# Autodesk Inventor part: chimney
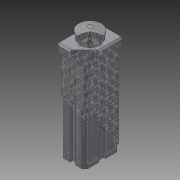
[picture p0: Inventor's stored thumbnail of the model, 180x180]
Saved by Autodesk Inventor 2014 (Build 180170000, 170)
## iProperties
Created: 2013-07
Part Number: chimney
Material: Generic
Document SubType Name: Modeling
Designer: Brent J. Rosenburgh
Density: 1 g/cm^3
Appearance: Default
Author: Brent J. Rosenburgh
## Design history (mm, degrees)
sketch "Sketch1"
  geometry: L1 (6.23, 11.74)-(-6.244, 11.74); L2 (-6.245, -11.748)-(-8.244, -9.708); L3 (-6.244, 11.74)-(-8.244, 9.74); L4 (8.23, 9.74)-(6.23, 11.74); L5 (6.23, -11.748)-(8.23, -9.748); L6 (-8.244, 2.133)-(-6.862, 2.133); L7 (-6.862, 2.133)-(-6.862, -0.609); L8 (-6.862, -0.609)-(-8.244, -1.991); L9 (8.23, 2.133)-(6.867, 2.133); L10 (6.867, 2.133)-(6.867, -0.609); L11 (6.867, -0.609)-(8.23, -1.972); L12 (-8.244, 9.74)-(-8.244, 2.133); L13 (-8.244, -1.991)-(-8.244, -9.708); L14 (8.23, -9.748)-(8.23, -1.972); L15 (8.23, 2.133)-(8.23, 9.74); L16 (-1.68, -11.748)-(-1.68, -9.875); L17 (-1.68, -9.875)-(1.667, -9.875); L18 (1.667, -9.875)-(1.667, -11.748); L19 (-6.245, -11.748)-(-1.68, -11.748); L20 (1.667, -11.748)-(6.23, -11.748); L21 (-2.966, 8.462)-(2.624, 8.462); L22 (4.624, 6.462)-(4.624, -6.141); L23 (2.624, -8.141)-(-2.966, -8.141); L24 (-4.966, -6.141)-(-4.966, 6.462); L25 (-2.966, 8.462)-(-4.966, 6.462); L26 (2.624, 8.462)-(4.624, 6.462); L27 (4.624, -6.141)-(2.624, -8.141); L28 (-2.966, -8.141)-(-4.966, -6.141); 1 further point
  constraints: 56 end point, 12 perpendicular, 11 parallel, 3 horizontal
extrude "Extrusion1" new body sketch "Sketch1" distance "d0" = 60; taper "d1" = 0 deg
sketch "Sketch2"
  geometry: L1 (-8.244, -9.708)-(-6.245, -11.748) reference; L2 (-1.68, -11.748)-(-1.68, -9.875) reference; L3 (-1.68, -9.875)-(1.667, -9.875) reference; L4 (1.667, -9.875)-(1.667, -11.748) reference; L5 (6.23, -11.748)-(8.23, -9.748) reference; L6 (-8.244, -1.991)-(-8.244, -9.708) reference; L7 (-8.244, -9.708)-(-8.244, -11.748); L8 (-8.244, -11.748)-(-6.245, -11.748); L9 (-1.68, -11.748)-(1.667, -11.748); L10 (6.23, -11.748)-(8.23, -11.748); L11 (8.23, -11.748)-(8.23, -9.748); 1 further point
  constraints: 10 end point, 3 collinear, 2 perpendicular
extrude "Extrusion2" join sketch "Sketch2" distance "d2" = 24; taper "d3" = 0 deg
chamfer "Chamfer2" distance "d7" = 1.8; stored, may be unused: second distance "d8" = 2, angle "d9" = 45 deg
sketch "Sketch3"
  geometry: L1 (0, 0)-(36, 0) reference; L2 (36, -2.04)-(36, 0) reference; L3 (36, -2.04)-(33.184, 0); 1 further point
  constraints: 2 end point, 1 point on line
extrude "Extrusion3" join sketch "Sketch3" distance "d10" = 16.47472; taper "d11" = 0 deg
sketch "Sketch4"
  geometry: L1 (8.23, -1.972)-(6.867, -0.609) reference; L2 (6.867, -0.609)-(6.867, 2.133) reference; L3 (6.867, 2.133)-(8.23, 2.133) reference; L4 (-8.244, 2.133)-(-6.862, 2.133) reference; L5 (-6.862, 2.133)-(-6.862, -0.609) reference; L6 (-6.862, -0.609)-(-8.244, -1.991) reference; L7 (-8.244, -1.991)-(-8.244, -11.748) reference; L8 (-8.244, 2.133)-(-8.244, -1.991); L9 (8.23, 2.133)-(8.23, -1.972); 1 further point
  constraints: 4 end point, 1 collinear, 1 parallel
extrude "Extrusion4" join sketch "Sketch4" distance "d12" = 38.02528; taper "d13" = 0 deg
sketch "Sketch5"
  geometry: L1 (33.184, 0)-(36, -2.04) reference; L2 (0, 11.841)-(21.975, 11.841) reference; L3 (21.975, 7.717)-(21.975, 11.841) reference; L4 (21.975, 7.717)-(16.281, 11.841); 1 further point
  constraints: 2 end point, 1 parallel, 1 point on line
extrude "Extrusion5" join sketch "Sketch5" distance "d14" = 2.22472; taper "d15" = 0 deg
sketch "Sketch6"
  geometry: L1 (-36, -2)-(-33.239, 0) reference; L2 (-21.975, 11.881)-(-21.975, 7.776) reference; L3 (0, 11.881)-(-21.975, 11.881) reference; L4 (-21.975, 7.776)-(-16.308, 11.881); 1 further point
  constraints: 2 end point, 1 parallel, 1 point on line
extrude "Extrusion6" join sketch "Sketch6" distance "d16" = 1.77528; taper "d17" = 0 deg
sketch "Sketch7"
  geometry: L1 (8.23, 9.74)-(6.23, 11.74) reference; L2 (-6.244, 11.74)-(-8.244, 9.74) reference; L3 (-8.244, 9.74)-(-8.244, -11.748) reference; L4 (-6.244, 11.74)-(-8.244, 11.74); L5 (-8.244, 11.74)-(-8.244, 9.74); L6 (6.23, 11.74)-(8.23, 11.74); L7 (8.23, 11.74)-(8.23, 9.74); 1 further point
  constraints: 8 end point, 4 perpendicular
extrude "Extrusion7" join sketch "Sketch7" distance "d18" = 54.47472; taper "d19" = 0 deg
sketch "Sketch8"
  geometry: L1 (5.525, 19.448)-(5.525, 21.448) reference; L2 (16.281, 11.841)-(21.975, 7.717) reference; L3 (0, 7.717)-(21.975, 7.717) reference; L4 (5.525, 19.448)-(2.764, 21.448); L5 (2.764, 21.448)-(5.525, 21.448); 1 further point
  constraints: 4 end point, 2 parallel
extrude "Extrusion8" join sketch "Sketch8" distance "d20" = 16.47472; taper "d21" = 0 deg
chamfer "Chamfer3" distance "d22" = 1.8; stored, may be unused: second distance "d23" = 2, angle "d24" = 45 deg
chamfer "Chamfer4" distance "d25" = 1.4; stored, may be unused: second distance "d26" = 2, angle "d27" = 45 deg
chamfer "Chamfer5" distance "d28" = 0.5; stored, may be unused: second distance "d29" = 2, angle "d30" = 45 deg
sketch "Sketch9"
  geometry: L1 (7.73, 11.74)-(8.23, 11.24) reference; L2 (7.73, 11.74)-(-7.744, 11.74) reference; L3 (-8.244, 11.24)-(-7.744, 11.74) reference; L4 (-8.244, 11.24)-(-8.244, -11.248) reference; L5 (-7.744, -11.748)-(-8.244, -11.248) reference; L6 (-7.744, -11.748)-(7.73, -11.748) reference; L7 (8.23, -11.248)-(7.73, -11.748) reference; L8 (8.23, -11.248)-(8.23, 11.24) reference; 1 further point
extrude "Extrusion9" join sketch "Sketch9" distance "d31" = 1.47472; taper "d32" = 45 deg
sketch "Sketch10"
  geometry: L1 (9.705, 11.851)-(9.705, -11.859) reference; L2 (8.341, 13.215)-(9.705, 11.851) reference; L3 (-8.355, 13.215)-(8.341, 13.215) reference; L4 (-9.719, 11.851)-(-8.355, 13.215) reference; L5 (-9.719, -11.859)-(-9.719, 11.851) reference; L6 (-8.355, -13.223)-(-9.719, -11.859) reference; L7 (8.341, -13.223)-(-8.355, -13.223) reference; L8 (9.705, -11.859)-(8.341, -13.223) reference; 1 further point
extrude "Extrusion10" join sketch "Sketch10" distance "d33" = 4; taper "d34" = 0 deg
sketch "Sketch11"
  geometry: L1 (9.705, -11.859)-(9.705, 11.851) reference; L2 (9.705, 11.851)-(8.341, 13.215) reference; L3 (8.341, 13.215)-(-8.355, 13.215) reference; L4 (-8.355, 13.215)-(-9.719, 11.851) reference; L5 (-9.719, 11.851)-(-9.719, -11.859) reference; L6 (-9.719, -11.859)-(-8.355, -13.223) reference; L7 (-8.355, -13.223)-(8.341, -13.223) reference; L8 (8.341, -13.223)-(9.705, -11.859) reference; 1 further point
extrude "Extrusion11" join sketch "Sketch11" distance "d35" = 1; taper "d36" = -45 deg
sketch "Sketch12"
  geometry: C1 r 5.597 at (0, 0); 1 further point
  constraints: 1 centre point, 1 coincident
extrude "Extrusion12" cut sketch "Sketch12" distance "d37" = 6.5; taper "d38" = 0 deg
chamfer "Chamfer6" distance "d39" = 0.5; stored, may be unused: second distance "d40" = 2, angle "d41" = 45 deg
chamfer "Chamfer7" distance "d42" = 5.5; stored, may be unused: second distance "d43" = 2, angle "d44" = 45 deg
chamfer "Chamfer8" distance "d45" = 5.75; stored, may be unused: second distance "d46" = 2, angle "d47" = 45 deg
sketch "Sketch13"
  geometry: L1 (0.5, -7)-(-0.5, -7); L2 (-0.5, -7)-(-0.5, 7); L3 (-0.5, 7)-(0.5, 7); L4 (0.5, 7)-(0.5, -7); L5 (0.5, -7)-(-0.5, 7); L6 (-0.5, -7)-(0.5, 7); L7 (-7, -0.5)-(7, -0.5); L8 (7, -0.5)-(7, 0.5); L9 (7, 0.5)-(-7, 0.5); L10 (-7, 0.5)-(-7, -0.5); L11 (4.596, -5.303)-(5.303, -4.596); L12 (5.303, -4.596)-(-4.596, 5.303); L13 (-5.303, 4.596)-(4.596, -5.303); L14 (-4.596, 5.303)-(-5.303, 4.596); L15 (4.596, 5.303)-(-5.303, -4.596); L16 (-5.303, -4.596)-(-4.596, -5.303); L17 (-4.596, -5.303)-(5.303, 4.596); L18 (5.303, 4.596)-(4.596, 5.303); C1 r 5.597 at (0, 0) reference
  constraints: 36 end point, 8 parallel, 4 perpendicular, 2 horizontal, 2 midpoint
  dimensions: "d48" = 1 distance of L2.end L3.end
extrude "Extrusion13" join sketch "Sketch13" distance "d49" = 4; taper "d50" = 0 deg
chamfer "Chamfer9" distance "d51" = 4.25; stored, may be unused: second distance "d52" = 2, angle "d53" = 45 deg
chamfer "Chamfer10" distance "d54" = 1; stored, may be unused: second distance "d55" = 2, angle "d56" = 45 deg
sketch "Sketch14"
  geometry: C1 r 7.018 at (0, 0); 1 further point
  constraints: 1 centre point, 1 coincident
extrude "Extrusion14" join sketch "Sketch14" distance "d57" = 0.6; taper "d58" = 45 deg
sketch "Sketch15"
  geometry: C1 r 7.618 at (0, 0) reference
extrude "Extrusion15" join sketch "Sketch15" distance "d59" = 1; taper "d60" = 0 deg
sketch "Sketch16"
  geometry: C1 r 7.618 at (0, 0) reference
extrude "Extrusion16" join sketch "Sketch16" distance "d61" = 2; taper "d62" = 0 deg
chamfer "Chamfer11" distance "d63" = 6; stored, may be unused: second distance "d64" = 2, angle "d65" = 45 deg
sketch "Sketch17"
  geometry: L1 (60, 23.948)-(56, 23.948); L2 (56, 23.948)-(56, 14.948); L3 (56, 14.948)-(60, 14.948); L4 (60, 14.948)-(60, 23.948); L5 (56, 14)-(56, 5); L6 (60, 14)-(56, 14); L7 (60, 5)-(60, 14); L8 (56, 5)-(60, 5); L9 (56, 4)-(56, -5); L10 (60, 4)-(56, 4); L11 (60, -5)-(60, 4); L12 (56, -5)-(60, -5); L13 (51, 18.779)-(51, 9.779); L14 (51, 28.727)-(51, 19.727); L15 (51, 8.779)-(51, -0.221); L16 (55, -0.221)-(55, 8.779); L17 (51, -0.221)-(55, -0.221); L18 (55, 8.779)-(51, 8.779); L19 (55, 9.779)-(55, 18.779); L20 (51, 9.779)-(55, 9.779); L21 (51, 19.727)-(55, 19.727); L22 (55, 28.727)-(51, 28.727); L23 (55, 19.727)-(55, 28.727); L24 (55, 18.779)-(51, 18.779); L25 (51, -1.111)-(51, -10.111); L26 (55, -10.111)-(55, -1.111); L27 (51, -10.111)-(55, -10.111); L28 (55, -1.111)-(51, -1.111); L29 (46, 14.948)-(50, 14.948); L30 (41, 18.779)-(41, 9.779); L31 (45, 9.779)-(45, 18.779); L32 (50, 14)-(46, 14); L33 (41, 9.779)-(45, 9.779); L34 (45, 8.779)-(41, 8.779); L35 (46, 14)-(46, 5); L36 (50, 5)-(50, 14); L37 (46, 5)-(50, 5); L38 (50, 4)-(46, 4); L39 (45, -0.221)-(45, 8.779); L40 (41, -0.221)-(45, -0.221); L41 (41, 8.779)-(41, -0.221); L42 (50, 23.948)-(46, 23.948); L43 (46, 23.948)-(46, 14.948); L44 (50, 14.948)-(50, 23.948); L45 (45, 18.779)-(41, 18.779); L46 (41, 19.727)-(45, 19.727); L47 (41, 28.727)-(41, 19.727); L48 (45, 19.727)-(45, 28.727); L49 (45, 28.727)-(41, 28.727); L50 (46, 4)-(46, -5); L51 (50, -5)-(50, 4); L52 (46, -5)-(50, -5); L53 (45, -1.111)-(41, -1.111); L54 (41, -1.111)-(41, -10.111); L55 (41, -10.111)-(45, -10.111); L56 (45, -10.111)-(45, -1.111); L57 (36, 14.948)-(40, 14.948); L58 (31, 18.779)-(31, 9.779); L59 (35, 9.779)-(35, 18.779); L60 (40, 14)-(36, 14); L61 (31, 9.779)-(35, 9.779); L62 (34.991, 8.791)-(31.009, 8.791); L63 (36, 14)-(36, 5); L64 (40, 5)-(40, 14)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; 1 further point
  constraints: 264 end point, 61 parallel, 33 horizontal, 29 perpendicular
  dimensions: "d66" = 9 distance of L2.end L1.end; "d67" = 9 distance of L5.end L5.start; "d68" = 9 distance of L9.end L9.start; "d69" = 9 distance of L14.end L14.start; "d70" = 9 distance of L13.end L13.start; "d71" = 9 distance of L15.end L15.start; "d72" = 9 distance of L25.end L25.start; "d73" = 9 distance of L29.start L42.end; "d74" = 9 distance of L35.end L32.end; "d75" = 9 distance of L50.end L38.end; "d76" = 9 distance of L46.start L47.start; "d77" = 9 distance of L30.end L30.start; "d78" = 9 distance of L40.start L34.end; "d79" = 9 distance of L54.end L53.end; "d80" = 9 distance of L57.start L70.end; "d81" = 9 distance of L63.end L60.end; "d82" = 9 distance of L78.end L66.end; "d83" = 9 distance of L74.start L75.start; "d84" = 9 distance of L58.end L58.start; "d87" = 9 distance of L83.start L85.end; "d88" = 9 distance of L97.start L82.end; "d90" = 9 distance of L81.start L87.start; "d91" = 9 distance of L90.end L90.start; "d94" = 9 distance of L102.start L104.end; "d97" = 9 distance of L100.start L106.start
extrude "Extrusion17" cut sketch "Sketch17" distance "d108" = 0.5; taper "d109" = 0 deg
sketch "Sketch18"
  geometry: L1 (-2.446, 60)-(7, 60); L2 (7, 60)-(7, 56); L3 (7, 56)-(-2.446, 56); L4 (-2.446, 56)-(-2.446, 60); L5 (7.912, 56)-(16.912, 56); L6 (16.912, 56)-(16.912, 60); L7 (16.912, 60)-(7.912, 60); L8 (7.912, 60)-(7.912, 56); L9 (5, 51)-(14.862, 51); L10 (14.862, 51)-(14.862, 55); L11 (14.862, 55)-(5, 55); L12 (5, 55)-(5, 51); L13 (-4.912, 55)-(4.088, 55); L14 (4.088, 51)-(-4.912, 51); L15 (4.088, 55)-(4.088, 51); L16 (-4.912, 51)-(-4.912, 55); L17 (8.326, 46)-(17.326, 46); L18 (17.326, 46)-(17.326, 50); L19 (17.326, 50)-(8.326, 50); L20 (8.326, 50)-(8.326, 46); L21 (-2.626, 50)-(7.414, 50); L22 (7.414, 46)-(-2.626, 46); L23 (7.414, 50)-(7.414, 46); L24 (-2.626, 46)-(-2.626, 50); L25 (6, 41)-(15, 41); L26 (15, 41)-(15, 45); L27 (15, 45)-(6, 45); L28 (6, 45)-(6, 41); L29 (5.088, 45)-(5.088, 41); L30 (5.088, 41)-(-3.912, 41); L31 (-3.912, 45)-(5.088, 45); L32 (-3.912, 41)-(-3.912, 45); L33 (7.912, 36.624)-(16.912, 36.624); L34 (16.912, 36.624)-(16.912, 40); L35 (16.912, 40)-(7.912, 40); L36 (7.912, 40)-(7.912, 36.624); L37 (7, 40)-(7, 36.654); L38 (7, 36.654)-(-2.386, 36.654); L39 (-2.386, 40)-(7, 40); L40 (-2.386, 36.654)-(-2.386, 40); L41 (-6, 60)-(18, 60); L42 (18, 60)-(18, 35); L43 (18, 35)-(-6, 35); L44 (-6, 35)-(-6, 60); 1 further point
  constraints: 88 end point, 22 parallel, 11 horizontal, 11 perpendicular
  dimensions: "d111" = 9 distance of L7.end L6.end; "d112" = 9 distance of L14.start L14.end; "d115" = 9 distance of L19.end L18.end; "d116" = 9 distance of L29.end L30.end; "d117" = 9 distance of L27.end L26.end; "d119" = 9 distance of L35.end L34.end
extrude "Extrusion18" cut sketch "Sketch18" distance "d120" = 0.5; taper "d121" = 0 deg
sketch "Sketch19"
  geometry: L1 (7, -56)-(16, -56); L2 (16, -56)-(16, -60); L3 (16, -60)-(7, -60); L4 (7, -60)-(7, -56); L5 (6, -56)-(-3.269, -56); L6 (-3.269, -56)-(-3.269, -60); L7 (-3.269, -60)-(6, -60); L8 (6, -60)-(6, -56); L9 (2, -51)-(11, -51); L10 (11, -51)-(11, -55); L11 (11, -55)-(2, -55); L12 (2, -55)-(2, -51); L13 (12, -51)-(21, -51); L14 (21, -51)-(21, -55); L15 (21, -55)-(12, -55); L16 (12, -55)-(12, -51); L17 (-8, -51)-(1, -51); L18 (1, -51)-(1, -55); L19 (1, -55)-(-8, -55); L20 (-8, -55)-(-8, -51); L21 (7, -46)-(16, -46); L22 (16, -46)-(16, -50); L23 (16, -50)-(7, -50); L24 (12, -45)-(12, -41); L25 (12, -41)-(21, -41); L26 (21, -45)-(12, -45); L27 (21, -41)-(21, -45); L28 (11, -41)-(11, -45); L29 (2, -41)-(11, -41); L30 (11, -45)-(2, -45); L31 (7, -50)-(7, -46); L32 (6, -50)-(6, -46); L33 (2, -45)-(2, -41); L34 (1, -41)-(1, -45); L35 (6, -46)-(-3.269, -46); L36 (-3.269, -50)-(6, -50); L37 (-3.269, -46)-(-3.269, -50); L38 (1, -45)-(-8, -45); L39 (-8, -41)-(1, -41); L40 (-8, -45)-(-8, -41); L41 (7, -36)-(16, -36); L42 (16, -36)-(16, -40); L43 (16, -40)-(7, -40); L44 (12, -35)-(12, -31); L45 (12, -31)-(21, -31); L46 (21, -35)-(12, -35); L47 (21, -31)-(21, -35); L48 (11, -31)-(11, -35); L49 (2, -31)-(11, -31); L50 (11, -35)-(2, -35); L51 (7, -40)-(7, -36); L52 (6, -40)-(6, -36); L53 (2, -35)-(2, -31); L54 (1, -31)-(1, -35); L55 (6, -36)-(-3.269, -36); L56 (-3.269, -40)-(6, -40); L57 (-3.269, -36)-(-3.269, -40); L58 (1, -35)-(-8, -35); L59 (-8, -31)-(1, -31); L60 (-8, -35)-(-8, -31); L61 (7, -26)-(16, -26); L62 (16, -26)-(16, -30); L63 (16, -30)-(7, -30); L64 (12, -25)-(12, -21)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
  constraints: 248 end point, 62 parallel, 31 horizontal, 31 perpendicular
extrude "Extrusion19" cut sketch "Sketch19" distance "d122" = 0.5; taper "d123" = 0 deg
sketch "Sketch20"
  geometry: L1 (-56, 14)-(-60, 14); L2 (-60, 14)-(-60, 5); L3 (-60, 5)-(-56, 5); L4 (-56, 5)-(-56, 14); L5 (-56, 24)-(-60, 24); L6 (-60, 24)-(-60, 15); L7 (-60, 15)-(-56, 15); L8 (-56, 15)-(-56, 24); L9 (-56, 4)-(-60, 4); L10 (-60, 4)-(-60, -5); L11 (-60, -5)-(-56, -5); L12 (-56, -5)-(-56, 4); L13 (-51, 9)-(-55, 9); L14 (-55, 9)-(-55, 0); L15 (-55, 0)-(-51, 0); L16 (-51, 0)-(-51, 9); L17 (-51, 19)-(-55, 19); L18 (-55, 19)-(-55, 10); L19 (-55, 10)-(-51, 10); L20 (-51, 10)-(-51, 19); L21 (-51, 29)-(-55, 29); L22 (-55, 29)-(-55, 20); L23 (-55, 20)-(-51, 20); L24 (-51, 20)-(-51, 29); L25 (-51, -1)-(-55, -1); L26 (-55, -1)-(-55, -10); L27 (-55, -10)-(-51, -10); L28 (-51, -10)-(-51, -1); L29 (-41, 0)-(-41, 9); L30 (-41, 9)-(-45, 9); L31 (-45, 9)-(-45, 0); L32 (-45, 0)-(-41, 0); L33 (-41, -1)-(-45, -1); L34 (-41, -10)-(-41, -1); L35 (-46, 5)-(-46, 14); L36 (-45, -10)-(-41, -10); L37 (-45, -1)-(-45, -10); L38 (-46, -5)-(-46, 4); L39 (-46, 14)-(-50, 14); L40 (-50, 14)-(-50, 5); L41 (-50, 4)-(-50, -5); L42 (-50, -5)-(-46, -5); L43 (-46, 4)-(-50, 4); L44 (-50, 5)-(-46, 5); L45 (-46, 24)-(-50, 24); L46 (-50, 24)-(-50, 15); L47 (-50, 15)-(-46, 15); L48 (-46, 15)-(-46, 24); L49 (-45, 10)-(-41, 10); L50 (-41, 19)-(-45, 19); L51 (-45, 19)-(-45, 10); L52 (-45, 20)-(-41, 20); L53 (-45, 29)-(-45, 20); L54 (-41, 29)-(-45, 29); L55 (-41, 20)-(-41, 29); L56 (-41, 10)-(-41, 19); L57 (-31, 1.571)-(-31, 9); L58 (-31, 9)-(-35, 9); L59 (-35, 9)-(-35, 0); L60 (-35, 0)-(-33.2, 0); L61 (-34.6, -1)-(-35, -1); L62 (-36, 5)-(-36, 14); L63 (-35, -1)-(-35, -1.286); L64 (-36, -5)-(-36, 4)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
  constraints: 262 end point, 57 parallel, 33 horizontal, 33 perpendicular
extrude "Extrusion20" cut sketch "Sketch20" distance "d124" = 0.5; taper "d125" = 0 deg
body "Solid1"
